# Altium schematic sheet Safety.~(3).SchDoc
size A
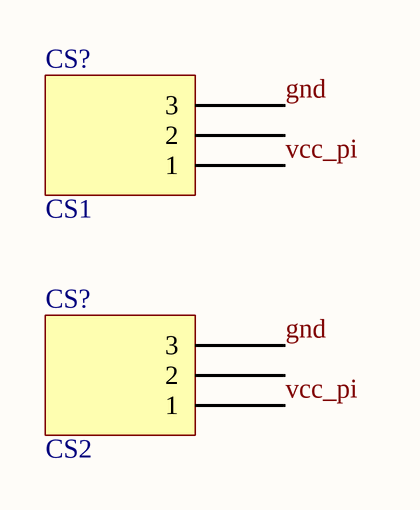
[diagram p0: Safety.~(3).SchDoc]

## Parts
(Parts that share a designator on the sheet are numbered #1, #2 ... from top to bottom, then left to right.)
CS?#1  CS1  [ACS712]
CS?#2  CS2  [ACS712]

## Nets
gnd: CS?#1.3 CS?#2.3
vcc_pi: CS?#1.1 CS?#2.1

Not connected (* = marked no-connect by the designer): CS?#1 2; CS?#2 2

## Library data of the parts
CS?#1 CS?#2 = ACS712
